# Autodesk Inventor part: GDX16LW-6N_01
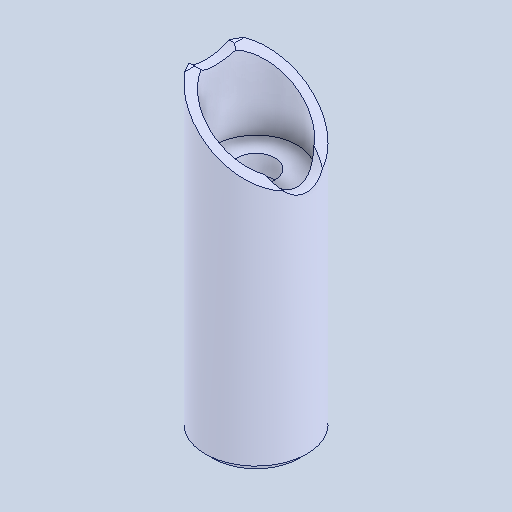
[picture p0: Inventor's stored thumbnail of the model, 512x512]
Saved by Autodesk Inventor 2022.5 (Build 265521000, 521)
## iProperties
Created: 2024-06
Part Number: GDX16LW-6N_01
Material: 一般
Document SubType Name: Modeling
Designer: ImaoCorp
Density: 1 g/cm^3
Appearance: 既定
Author: ImaoCorp
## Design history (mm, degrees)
feature "GDX16LW-6N_01"
node "ソリッド1"
